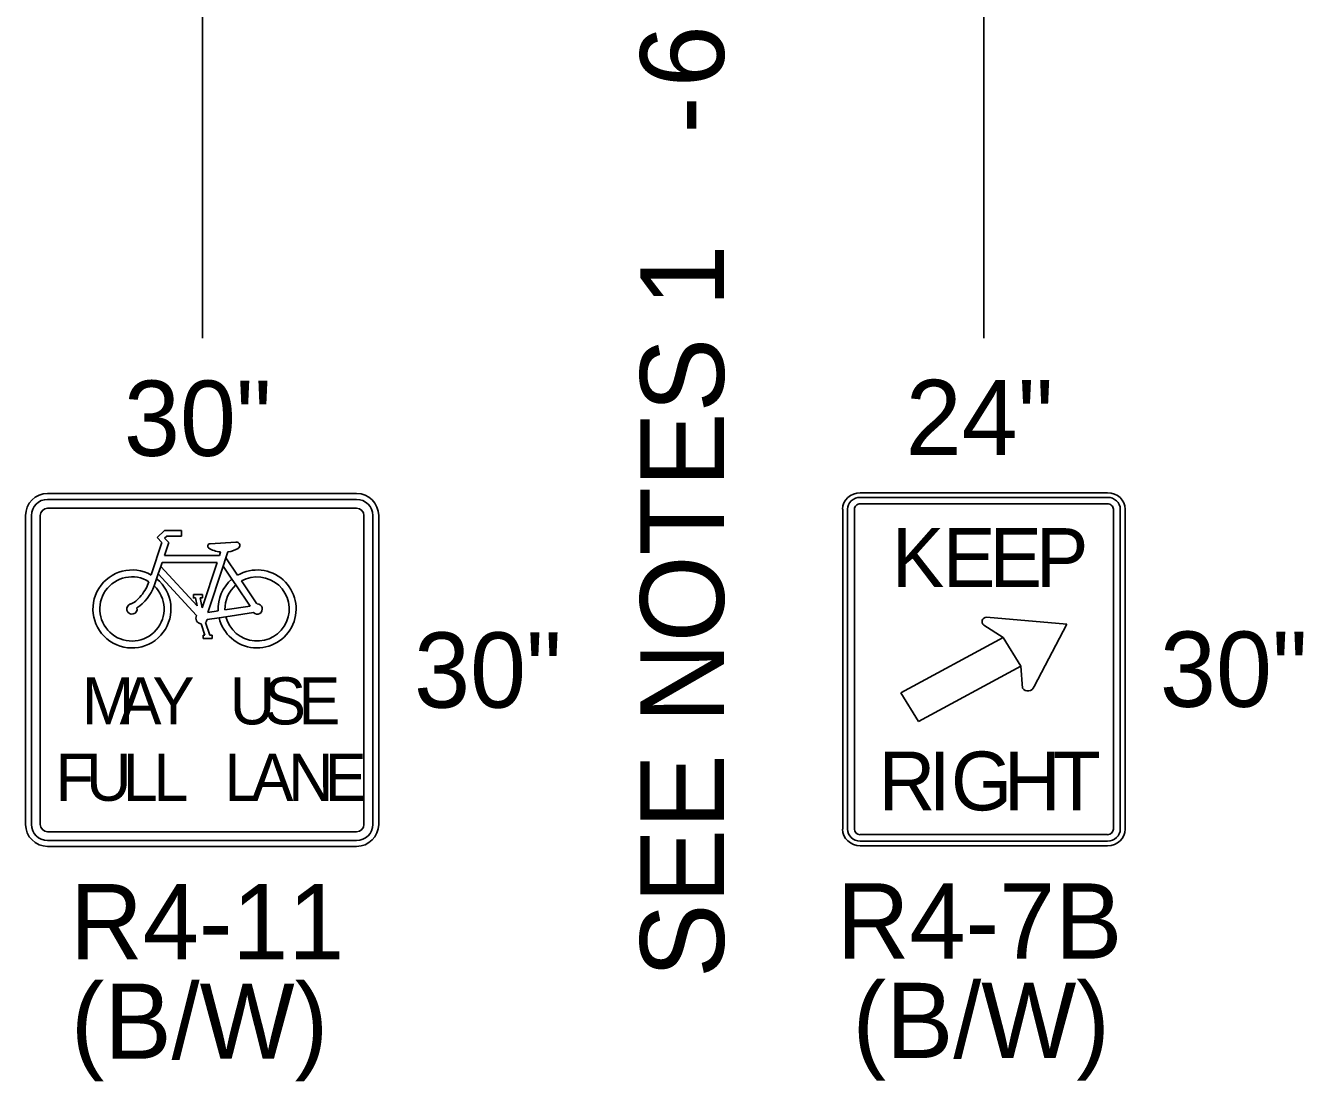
# Model space of a CAD drawing. Extents: x 99982 to 100176, y 99905 to 100011.
# Drawn here: x 100010.522 to 100011.744, y 99975.128 to 99976.138 of the extents above; entities that cross this region are included whole.
import ezdxf

# ---------------------------------------------------------------- set-up
doc = ezdxf.new("R2010")
doc.units = 0
for name, color, linetype in [('TR_SN_ConstructionSigns', 7, 'Continuous'), ('TR_WZ_WorkZoneDetails', 7, 'Continuous'), ('TR_WZ_WorkZoneTextCurrent', 7, 'Continuous')]:
    doc.layers.add(name, color=color, linetype=linetype)

msp = doc.modelspace()

# ---------------------------------------------------------------- linework, layer by layer
at = {"layer": 'TR_SN_ConstructionSigns'}
for p, q in [((100010.5435, 99975.6906), (100010.8388, 99975.6906)), ((100010.8388, 99975.6906), (100010.5435, 99975.6906)), ((100010.8388, 99975.6906), (100010.5435, 99975.6906)), ((100010.8388, 99975.6849), (100010.5435, 99975.6849)), ((100011.3202, 99975.6913), (100011.5565, 99975.6913)), ((100011.5565, 99975.6913), (100011.3202, 99975.6913)), ((100011.5565, 99975.6869), (100011.3202, 99975.6869)), ((100010.5224, 99975.3742), (100010.5224, 99975.6695)), ((100010.5224, 99975.6695), (100010.5224, 99975.3742)), ((100010.5224, 99975.6695), (100010.5224, 99975.3742)), ((100010.528, 99975.6695), (100010.528, 99975.3742)), ((100010.5365, 99975.3742), (100010.5365, 99975.6695)), ((100010.5435, 99975.6765), (100010.8388, 99975.6765)), ((100010.8458, 99975.6695), (100010.8458, 99975.3742)), ((100010.8543, 99975.3742), (100010.8543, 99975.6695)), ((100010.8599, 99975.6695), (100010.8599, 99975.3742)), ((100010.8599, 99975.3742), (100010.8599, 99975.6695)), ((100010.8599, 99975.3742), (100010.8599, 99975.6695)), ((100011.3034, 99975.3696), (100011.3034, 99975.6755)), ((100011.3034, 99975.6755), (100011.3034, 99975.3696)), ((100011.308, 99975.6755), (100011.308, 99975.3696)), ((100011.3146, 99975.3696), (100011.3146, 99975.6755)), ((100011.3202, 99975.6808), (100011.5565, 99975.6808)), ((100011.5621, 99975.6755), (100011.5621, 99975.3696)), ((100011.5687, 99975.3696), (100011.5687, 99975.6755)), ((100011.5734, 99975.6755), (100011.5734, 99975.3696)), ((100011.5734, 99975.3696), (100011.5734, 99975.6755)), ((100010.6552, 99975.6554), (100010.6482, 99975.6484)), ((100010.6482, 99975.6484), (100010.6528, 99975.6438)), ((100010.6716, 99975.6554), (100010.6552, 99975.6554)), ((100010.6553, 99975.6478), (100010.6574, 99975.6499)), ((100010.6592, 99975.6438), (100010.6553, 99975.6478)), ((100010.6574, 99975.6499), (100010.6716, 99975.6499)), ((100010.6716, 99975.6499), (100010.6716, 99975.6554)), ((100010.6528, 99975.6438), (100010.6425, 99975.6127)), ((100010.6551, 99975.6313), (100010.6592, 99975.6438)), ((100010.7235, 99975.6442), (100010.6987, 99975.6425)), ((100010.7088, 99975.6347), (100010.7077, 99975.6313)), ((100010.7138, 99975.629), (100010.7158, 99975.6348)), ((100010.6492, 99975.6138), (100010.6516, 99975.6209)), ((100010.6516, 99975.6209), (100010.6529, 99975.6247)), ((100010.6863, 99975.5833), (100010.6516, 99975.6209)), ((100010.6529, 99975.6247), (100010.7055, 99975.6247)), ((100010.7077, 99975.6313), (100010.6551, 99975.6313)), ((100010.7055, 99975.6247), (100010.6911, 99975.5814)), ((100010.6965, 99975.5769), (100010.7112, 99975.6211)), ((100010.7138, 99975.629), (100010.7112, 99975.6211)), ((100010.7112, 99975.6211), (100010.7196, 99975.6087)), ((100010.725, 99975.6125), (100010.7138, 99975.629)), ((100010.6477, 99975.6091), (100010.6454, 99975.6023)), ((100010.6477, 99975.6091), (100010.6492, 99975.6138)), ((100010.6492, 99975.6138), (100010.6859, 99975.574)), ((100010.7196, 99975.6087), (100010.7234, 99975.6032)), ((100010.7234, 99975.6032), (100010.7372, 99975.5829)), ((100010.7436, 99975.5851), (100010.7287, 99975.607)), ((100010.6915, 99975.594), (100010.6828, 99975.594)), ((100010.6849, 99975.5907), (100010.6863, 99975.5833)), ((100010.6911, 99975.5814), (100010.6894, 99975.5907)), ((100010.6894, 99975.5907), (100010.6915, 99975.5907)), ((100010.6915, 99975.5907), (100010.6915, 99975.594)), ((100010.696, 99975.5702), (100010.7073, 99975.5718)), ((100010.7064, 99975.5783), (100010.6965, 99975.5769)), ((100010.7073, 99975.5718), (100010.7139, 99975.5728)), ((100010.7372, 99975.5829), (100010.713, 99975.5793)), ((100010.7139, 99975.5728), (100010.7402, 99975.5767)), ((100011.4407, 99975.5725), (100011.5177, 99975.5656)), ((100010.6902, 99975.5659), (100010.6938, 99975.5551)), ((100010.6984, 99975.5551), (100010.6943, 99975.5673)), ((100011.4567, 99975.5529), (100011.4382, 99975.5647)), ((100011.5177, 99975.5656), (100011.4863, 99975.506)), ((100010.6938, 99975.5551), (100010.692, 99975.5551)), ((100010.692, 99975.5551), (100010.692, 99975.5518)), ((100010.692, 99975.5518), (100010.7007, 99975.5518)), ((100010.7007, 99975.5551), (100010.6984, 99975.5551)), ((100010.7007, 99975.5518), (100010.7007, 99975.5551)), ((100011.4567, 99975.5529), (100011.359, 99975.5)), ((100011.4736, 99975.5255), (100011.4567, 99975.5529)), ((100011.4736, 99975.5255), (100011.4567, 99975.5529)), ((100011.4567, 99975.5529), (100011.4567, 99975.5529)), ((100011.3758, 99975.4726), (100011.4736, 99975.5255)), ((100011.4752, 99975.5045), (100011.4736, 99975.5255)), ((100011.4736, 99975.5255), (100011.4736, 99975.5255)), ((100011.359, 99975.5), (100011.3758, 99975.4726)), ((100010.8388, 99975.3671), (100010.5435, 99975.3671)), ((100011.5565, 99975.3644), (100011.3202, 99975.3644)), ((100010.5435, 99975.3587), (100010.8388, 99975.3587)), ((100010.8388, 99975.3531), (100010.5435, 99975.3531)), ((100010.5435, 99975.3531), (100010.8388, 99975.3531)), ((100010.5435, 99975.3531), (100010.8388, 99975.3531)), ((100011.3202, 99975.3582), (100011.5565, 99975.3582)), ((100011.5565, 99975.3538), (100011.3202, 99975.3538)), ((100011.3202, 99975.3538), (100011.5565, 99975.3538))]:
    msp.add_line(p, q, dxfattribs=at)
msp.add_lwpolyline([(100010.6828, 99975.594), (100010.6828, 99975.5907), (100010.6849, 99975.5907)], dxfattribs=at)
for centre, radius, start, end in [((100010.5435, 99975.6695), 0.0211, 90, 180), ((100010.5435, 99975.6695), 0.0211, 90, 180), ((100010.5435, 99975.6695), 0.0211, 90, 180), ((100010.5435, 99975.6695), 0.0155, 90, 180), ((100010.8388, 99975.6695), 0.0211, 0, 90), ((100010.8388, 99975.6695), 0.0211, 0, 90), ((100010.8388, 99975.6695), 0.0211, 0, 90), ((100010.8388, 99975.6695), 0.0155, 0, 90), ((100010.5435, 99975.6695), 0.00703, 90, 180), ((100010.8388, 99975.6695), 0.00703, 0, 90), ((100010.6987, 99975.6403), 0.00219, 89.3854, 243.6828), ((100010.7239, 99975.6409), 0.00329, 294.5519, 96.4128), ((100010.6241, 99975.5802), 0.0373, 60.5529, 50.868), ((100010.6241, 99975.5802), 0.0307, 58.1532, 46.1649), ((100010.7437, 99975.5802), 0.0373, 130.0889, 182.8379), ((100010.7437, 99975.5802), 0.0373, 192.9622, 119.9648), ((100010.7437, 99975.5802), 0.0307, 193.937, 119.0598), ((100010.7437, 99975.5802), 0.0307, 131.3616, 181.6359), ((100010.6241, 99975.5802), 0.00493, 105.257, 14.3233), ((100010.7437, 99975.5802), 0.00493, 225.1095, 90.4672), ((100010.6907, 99975.5714), 0.00548, 151.1744, 264.8566), ((100010.6907, 99975.5714), 0.00548, 312.0053, 347.2932), ((100010.5435, 99975.3742), 0.0211, 180, 270), ((100010.5435, 99975.3742), 0.0211, 180, 270), ((100010.5435, 99975.3742), 0.0211, 180, 270), ((100010.5435, 99975.3742), 0.0155, 180, 270), ((100010.5435, 99975.3742), 0.00703, 180, 270), ((100010.8388, 99975.3742), 0.0211, 270, 0), ((100010.8388, 99975.3742), 0.0211, 270, 0), ((100010.8388, 99975.3742), 0.0155, 270, 0), ((100010.8388, 99975.3742), 0.00703, 270, 0), ((100010.8388, 99975.3742), 0.0211, 270, 0)]:
    msp.add_arc(centre, radius, start, end, dxfattribs=at)
for centre, major_axis, ratio, start_param, end_param in [((100011.3202, 99975.6755), (-0.0169, 0), 0.9375, 4.712389, 6.283185), ((100011.3202, 99975.6755), (-0.0169, 0), 0.9375, 4.712389, 6.283185), ((100011.3202, 99975.6755), (0.0122, 0), 0.9375, 1.570796, 3.141593), ((100011.5565, 99975.6755), (-0.0169, 0), 0.9375, 3.141593, 4.712389), ((100011.5565, 99975.6755), (-0.0169, 0), 0.9375, 3.141593, 4.712389), ((100011.5565, 99975.6755), (0.0122, 0), 0.9375, 0, 1.570796), ((100011.3202, 99975.6755), (0.00563, 0), 0.9375, 1.570796, 3.141593), ((100011.5565, 99975.6755), (0.00562, 0), 0.9375, 6.283185, 7.853982), ((100010.7118, 99975.6455), (-0.0186, 0), 0.588235, 0.686048, 1.410588), ((100010.7118, 99975.6455), (-0.0186, 0), 0.588235, 1.786993, 2.401245), ((100010.629, 99975.6009), (-0.0105, -0.0158), 0.413554, 0.494612, 2.170849), ((100010.629, 99975.6009), (-0.014, -0.021), 0.55814, 0.868091, 1.989998), ((100011.4415, 99975.568), (0.00485, -0.00001), 0.937492, 1.73335, 3.955171), ((100011.4804, 99975.5075), (0.00607, -0.00002), 0.9368, 3.700197, 6.020834), ((100011.3202, 99975.3696), (0.0169, 0), 0.9375, 3.141593, 4.712389), ((100011.3202, 99975.3696), (0.0169, 0), 0.9375, 3.141593, 4.712389), ((100011.3202, 99975.3696), (0.0122, 0), 0.9375, 3.141593, 4.712389), ((100011.3202, 99975.3696), (0.00563, 0), 0.9375, 3.141593, 4.712389), ((100011.5565, 99975.3696), (0.0169, 0), 0.9375, 4.712389, 6.283185), ((100011.5565, 99975.3696), (0.0122, 0), 0.9375, 4.712389, 6.283185), ((100011.5565, 99975.3696), (0.00562, 0), 0.9375, 4.712389, 6.283185), ((100011.5565, 99975.3696), (0.0169, 0), 0.9375, 4.712389, 6.283185)]:
    msp.add_ellipse(centre, major_axis=major_axis, ratio=ratio, start_param=start_param, end_param=end_param, dxfattribs=at)
at = {"layer": 'TR_WZ_WorkZoneDetails'}
for p, q in [((100011.4384, 99976.2797), (100011.4384, 99975.8393)), ((100010.6914, 99976.2577), (100010.6914, 99975.8393))]:
    msp.add_line(p, q, dxfattribs=at)

# ---------------------------------------------------------------- texts
at = {"layer": 'TR_SN_ConstructionSigns'}
for s, p in [('30"', (100010.6164, 99975.7266)), ('24"', (100011.3636, 99975.7273)), ('30"', (100010.8937, 99975.4858)), ('30"', (100011.6066, 99975.4866)), ('R4-11', (100010.5649, 99975.2451)), ('R4-7B', (100011.2977, 99975.2458)), ('(B/W)', (100010.5657, 99975.15)), ('(B/W)', (100011.3128, 99975.1507))]:
    msp.add_text(s, height=0.072, rotation=360, dxfattribs=at).set_placement(p)
for s, height, p in [('K', 0.0562, (100011.3503, 99975.6013)), ('E', 0.0562, (100011.3993, 99975.6013)), ('E', 0.0562, (100011.4437, 99975.6013)), ('P', 0.0562, (100011.4881, 99975.6013)), ('M', 0.045, (100010.5762, 99975.4698)), ('A', 0.045, (100010.6122, 99975.4698)), ('Y', 0.045, (100010.6437, 99975.4698)), ('U', 0.045, (100010.7175, 99975.4698)), ('S', 0.045, (100010.7503, 99975.4698)), ('E', 0.045, (100010.7832, 99975.4698)), ('F', 0.045, (100010.551, 99975.3967)), ('U', 0.045, (100010.5802, 99975.3967)), ('L', 0.045, (100010.6153, 99975.3967)), ('L', 0.045, (100010.6446, 99975.3967)), ('L', 0.045, (100010.7125, 99975.3967)), ('A', 0.045, (100010.7382, 99975.3967)), ('N', 0.045, (100010.7733, 99975.3967)), ('E', 0.045, (100010.8084, 99975.3967)), ('R', 0.0562, (100011.3377, 99975.3876)), ('I', 0.0562, (100011.3855, 99975.3876)), ('G', 0.0562, (100011.4069, 99975.3876)), ('H', 0.0562, (100011.4575, 99975.3876)), ('T', 0.0562, (100011.5042, 99975.3876))]:
    msp.add_text(s, height=height, dxfattribs=at).set_placement(p)
at = {"layer": 'TR_WZ_WorkZoneTextCurrent'}
for s, p in [('6', (100011.1899, 99976.079)), ('-', (100011.1899, 99976.0349)), ('SEE NOTES 1', (100011.1899, 99975.2272))]:
    msp.add_text(s, height=0.08, rotation=90, dxfattribs=at).set_placement(p)

doc.saveas('drawing.dxf')
